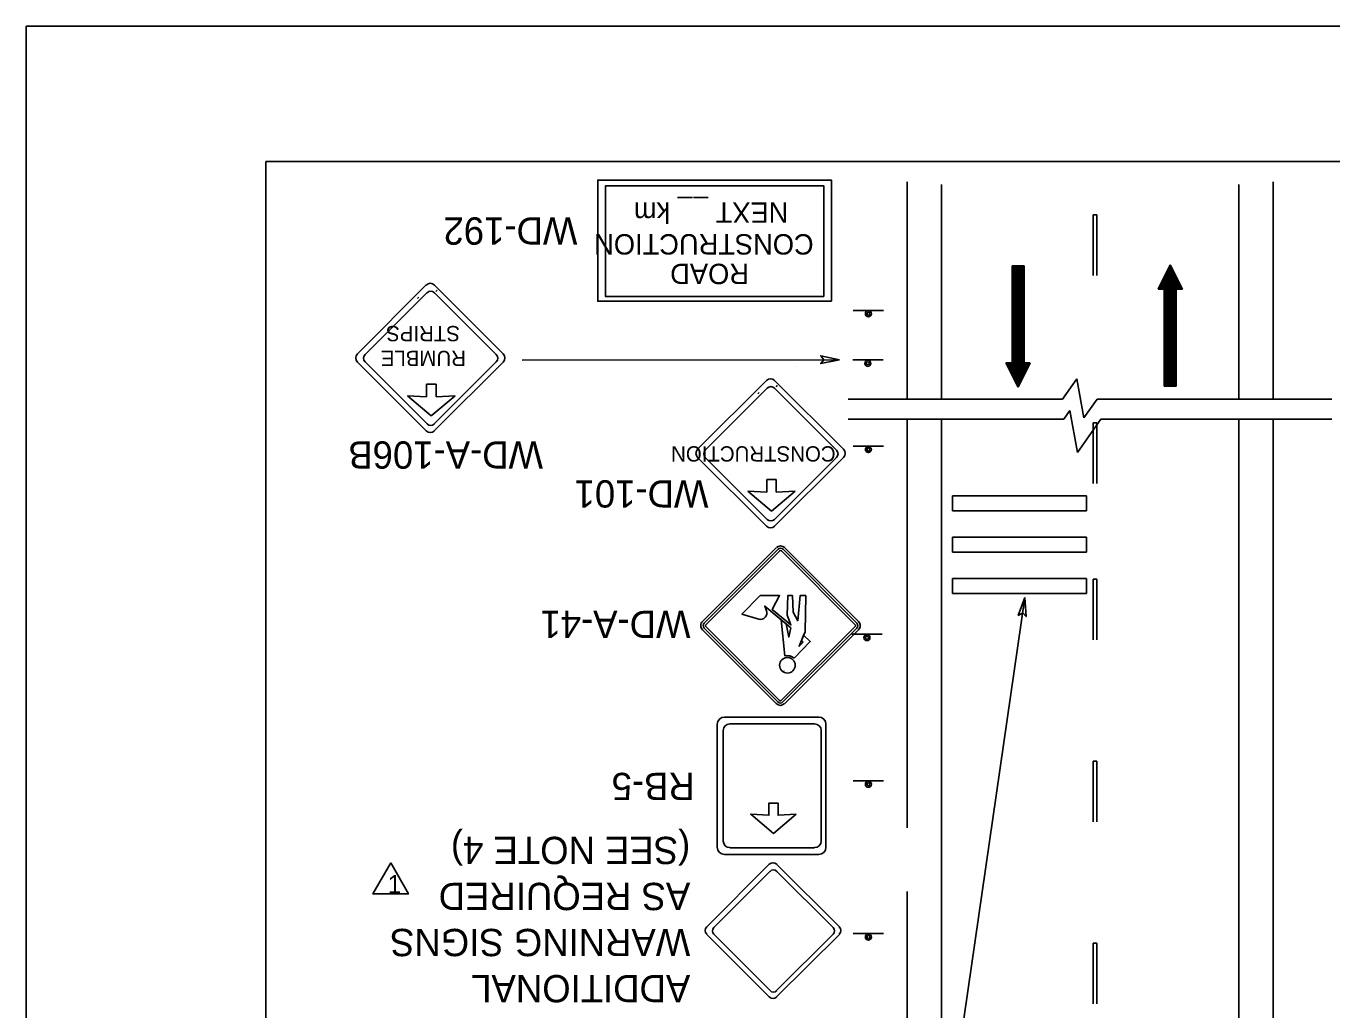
# Model space of a CAD drawing. Extents: x 1372 to 1588, y 125 to 404.
# Drawn here: x 1372.1 to 1476.2, y 325.5 to 404 of the extents above; entities that cross this region are included whole.
import ezdxf

# ---------------------------------------------------------------- set-up
doc = ezdxf.new("R2010")
doc.units = 0
for name, color, linetype in [('Level 1', 7, 'Continuous'), ('Level 10', 7, 'Continuous'), ('Level 2', 7, 'Continuous'), ('Level 44', 7, 'Continuous'), ('Level 5', 7, 'Continuous'), ('Level 60', 7, 'Continuous')]:
    doc.layers.add(name, color=color, linetype=linetype)

msp = doc.modelspace()

# ---------------------------------------------------------------- linework, layer by layer
at = {"layer": 'Level 1'}
for p, q in [((1431.88, 362.39), (1426, 356.51)), ((1438.43, 356.51), (1432.55, 362.39)), ((1432.02, 362.26), (1426.13, 356.38)), ((1432.15, 362.13), (1426.26, 356.25)), ((1438.17, 356.24), (1432.29, 362.13)), ((1438.3, 356.38), (1432.42, 362.26)), ((1426, 355.85), (1431.88, 349.96)), ((1426.13, 355.98), (1432.01, 350.09)), ((1426.26, 356.11), (1432.14, 350.22)), ((1432.28, 350.22), (1438.17, 356.1)), ((1432.41, 350.09), (1438.3, 355.97)), ((1432.55, 349.96), (1438.43, 355.84)), ((1432.49, 352.54), (1432.5, 352.54))]:
    msp.add_line(p, q, dxfattribs=at)
for points in [[(1430.49, 356.69), (1429.14, 357.1), (1430.6, 358.57), (1432.14, 358.57), (1431.56, 357.46), (1433.05, 356.24), (1432.76, 357.02), (1432.8, 358.57), (1433.16, 358.57), (1433.23, 357.25), (1433.59, 356.57), (1433.78, 358.57), (1434.23, 358.57), (1434.17, 355.69), (1433.7, 354.53), (1434.03, 354.87)], [(1430.49, 356.69), (1429.14, 357.1), (1430.6, 358.57), (1432.14, 358.57), (1431.56, 357.46), (1433.05, 356.24), (1432.76, 357.02), (1432.8, 358.57), (1433.16, 358.57), (1433.23, 357.25), (1433.59, 356.57), (1433.78, 358.57), (1434.23, 358.57), (1434.17, 355.69), (1433.7, 354.53), (1434.03, 354.87)], [(1430.49, 356.69), (1429.14, 357.1), (1430.6, 358.57), (1432.14, 358.57), (1431.56, 357.46), (1433.05, 356.24), (1432.76, 357.02), (1432.8, 358.57), (1433.16, 358.57), (1433.23, 357.25), (1433.59, 356.57)], [(1433.59, 356.57), (1433.78, 358.57), (1434.23, 358.57), (1434.17, 355.69), (1434.06, 355.41), (1434.59, 354.91), (1433.31, 353.58)], [(1432.57, 353.77), (1432.27, 356.64), (1432.66, 356.33), (1432.88, 355.26), (1433.05, 356), (1430.96, 357.73), (1431.1, 357.36)], [(1432.57, 353.77), (1432.27, 356.64), (1432.66, 356.33), (1432.88, 355.26), (1433.05, 356), (1430.96, 357.73), (1431.1, 357.36)], [(1432.57, 353.77), (1432.27, 356.64), (1430.96, 357.73), (1431.1, 357.36)], [(1434.03, 354.87), (1433.89, 354.99), (1434.06, 355.41), (1434.59, 354.91), (1433.31, 353.58)], [(1434.03, 354.87), (1433.89, 354.99), (1434.06, 355.41), (1434.59, 354.91), (1433.31, 353.58)]]:
    msp.add_lwpolyline(points, dxfattribs=at)
for points in [[(1432.66, 356.33), (1432.88, 355.26), (1433.05, 356)], [(1434.03, 354.87), (1433.89, 354.99), (1433.7, 354.53)], [(1401.13, 337.26), (1399.71, 334.79), (1402.55, 334.79)]]:
    msp.add_lwpolyline(points, close=True, dxfattribs=at)
msp.add_circle((1432.77, 353.02), 0.624, dxfattribs=at)
msp.add_circle((1432.77, 353.02), 0.624, dxfattribs=at)
msp.add_circle((1432.77, 353.02), 0.624, dxfattribs=at)
for centre, radius, start, end in [((1432.22, 362.06), 0.471, 45, 134.9652), ((1432.22, 362.06), 0.285, 45, 134.9652), ((1432.22, 362.06), 0.1, 45, 134.9652), ((1430.63, 357.18), 0.502, 253.381, 21.0999), ((1430.63, 357.18), 0.502, 253.381, 21.0999), ((1430.63, 357.18), 0.502, 253.381, 21.0999), ((1426.33, 356.18), 0.471, 134.9651, 225), ((1426.33, 356.18), 0.285, 134.9651, 225), ((1426.33, 356.18), 0.1, 134.9651, 225), ((1438.1, 356.17), 0.1, 314.965, 45), ((1438.1, 356.17), 0.285, 314.965, 45), ((1438.1, 356.17), 0.471, 314.965, 45), ((1432.77, 353.02), 0.775, 46.3135, 104.9576), ((1432.77, 353.02), 0.775, 46.3135, 104.9576), ((1432.77, 353.02), 0.775, 46.3135, 104.9576), ((1432.21, 350.29), 0.471, 225, 314.9651), ((1432.21, 350.29), 0.285, 225, 314.9651), ((1432.21, 350.29), 0.1, 225, 314.9651)]:
    msp.add_arc(centre, radius, start, end, dxfattribs=at)
at = {"layer": 'Level 10'}
for p, q in [((1442.33, 391.56), (1442.33, 374.24)), ((1471.51, 391.56), (1471.51, 374.24)), ((1445.05, 391.35), (1445.05, 374.24)), ((1468.76, 391.35), (1468.76, 374.24)), ((1450.68, 377.12), (1450.68, 384.86)), ((1451.65, 384.86), (1450.68, 384.86)), ((1450.68, 376.15), (1450.68, 384.86)), ((1450.8, 375.91), (1450.8, 384.86)), ((1450.92, 375.67), (1450.92, 384.86)), ((1451.04, 375.42), (1451.04, 384.86)), ((1451.16, 375.18), (1451.16, 384.86)), ((1451.28, 375.42), (1451.28, 384.86)), ((1451.4, 375.67), (1451.4, 384.86)), ((1451.52, 375.91), (1451.52, 384.86)), ((1451.65, 377.12), (1451.65, 384.86)), ((1451.65, 376.15), (1451.65, 384.86)), ((1463.3, 384.94), (1462.33, 383)), ((1463.06, 384.45), (1463.06, 375.26)), ((1463.18, 384.69), (1463.18, 375.26)), ((1463.3, 384.94), (1463.3, 375.26)), ((1463.3, 384.94), (1464.27, 383)), ((1463.42, 384.69), (1463.42, 375.26)), ((1463.54, 384.45), (1463.54, 375.26)), ((1462.45, 383.24), (1462.45, 383)), ((1462.57, 383.49), (1462.57, 383)), ((1462.69, 383.73), (1462.69, 383)), ((1462.82, 383.97), (1462.82, 375.26)), ((1462.94, 384.21), (1462.94, 375.26)), ((1463.66, 384.21), (1463.66, 375.26)), ((1463.78, 383.97), (1463.78, 375.26)), ((1463.9, 383.73), (1463.9, 383)), ((1464.03, 383.49), (1464.03, 383)), ((1464.15, 383.24), (1464.15, 383)), ((1462.33, 383), (1462.82, 383)), ((1462.82, 383), (1462.82, 375.26)), ((1463.78, 383), (1463.78, 375.26)), ((1463.78, 383), (1464.27, 383)), ((1451.16, 375.18), (1450.19, 377.12)), ((1450.68, 377.12), (1450.19, 377.12)), ((1450.32, 376.87), (1450.32, 377.12)), ((1450.44, 376.63), (1450.44, 377.12)), ((1450.56, 376.39), (1450.56, 377.12)), ((1451.16, 375.18), (1452.13, 377.12)), ((1452.13, 377.12), (1451.65, 377.12)), ((1451.77, 376.39), (1451.77, 377.12)), ((1451.89, 376.63), (1451.89, 377.12)), ((1452.01, 376.87), (1452.01, 377.12)), ((1462.82, 375.26), (1463.78, 375.26)), ((1442.33, 372.63), (1442.33, 340.05)), ((1445.05, 372.63), (1445.05, 157.87)), ((1468.76, 372.63), (1468.76, 157.87)), ((1471.51, 372.63), (1471.51, 202.79)), ((1456.61, 366.53), (1445.93, 366.53)), ((1445.93, 366.53), (1445.93, 365.33)), ((1456.61, 365.33), (1456.61, 366.53)), ((1445.93, 365.33), (1456.61, 365.33)), ((1445.93, 362.03), (1445.93, 363.23)), ((1445.93, 363.23), (1456.61, 363.23)), ((1456.61, 363.23), (1456.61, 362.03)), ((1456.61, 362.03), (1445.93, 362.03)), ((1456.61, 359.93), (1445.93, 359.93)), ((1445.93, 359.93), (1445.93, 358.73)), ((1456.61, 358.73), (1456.61, 359.93)), ((1445.93, 358.73), (1456.61, 358.73)), ((1442.33, 157.87), (1442.33, 334.98))]:
    msp.add_line(p, q, dxfattribs=at)
at = {"layer": 'Level 2'}
for p, q in [((1457.15, 388.93), (1457.15, 384.09)), ((1457.44, 388.93), (1457.15, 388.93)), ((1457.44, 384.09), (1457.44, 388.93)), ((1403.27, 382.26), (1403.37, 382.37)), ((1404.73, 382.83), (1404.83, 382.93)), ((1431.86, 375.22), (1431.96, 375.32)), ((1430.4, 374.65), (1430.51, 374.76)), ((1457.15, 372.34), (1457.15, 367.5)), ((1457.44, 372.34), (1457.15, 372.34)), ((1457.44, 367.5), (1457.44, 372.34)), ((1457.15, 359.87), (1457.15, 355.04)), ((1457.44, 359.87), (1457.15, 359.87)), ((1457.44, 355.04), (1457.44, 359.87)), ((1457.15, 345.36), (1457.15, 340.52)), ((1457.44, 345.36), (1457.15, 345.36)), ((1457.44, 340.52), (1457.44, 345.36)), ((1457.15, 330.85), (1457.15, 326.01)), ((1457.44, 330.85), (1457.15, 330.85)), ((1457.44, 326.01), (1457.44, 330.85))]:
    msp.add_line(p, q, dxfattribs=at)
for points in [[(1436.27, 382.04), (1417.64, 382.04), (1417.64, 391.7), (1436.27, 391.7)], [(1435.68, 382.42), (1418.26, 382.42), (1418.26, 391.23), (1435.68, 391.23)]]:
    msp.add_lwpolyline(points, close=True, dxfattribs=at)
at = {"layer": 'Level 44'}
for p, q in [((1403.96, 383.34), (1398.48, 377.85)), ((1410.1, 377.85), (1404.61, 383.34)), ((1399.09, 377.79), (1404.03, 382.73)), ((1404.61, 382.73), (1409.55, 377.79)), ((1440.44, 381.31), (1438.02, 381.31)), ((1398.48, 377.19), (1403.96, 371.71)), ((1404.03, 372.26), (1399.09, 377.2)), ((1409.55, 377.2), (1404.61, 372.26)), ((1404.61, 371.71), (1410.1, 377.19)), ((1410.1, 377.85), (1410.1, 377.85)), ((1440.4, 377.36), (1437.98, 377.36)), ((1433.44, 376.82), (1433.44, 376.82)), ((1404.75, 375.43), (1403.99, 375.43)), ((1403.99, 375.43), (1403.99, 374.42)), ((1404.75, 374.42), (1404.75, 375.43)), ((1431.09, 375.73), (1425.61, 370.24)), ((1426.22, 370.18), (1431.16, 375.12)), ((1437.24, 370.24), (1431.74, 375.73)), ((1431.74, 375.12), (1436.69, 370.18)), ((1454.71, 374.24), (1455.85, 375.86)), ((1455.85, 375.86), (1456.41, 372.74)), ((1403.99, 374.42), (1402.48, 374.5)), ((1402.48, 374.5), (1404.37, 372.91)), ((1404.37, 372.91), (1406.26, 374.5)), ((1406.26, 374.5), (1404.75, 374.42)), ((1437.62, 374.24), (1454.71, 374.24)), ((1456.41, 372.74), (1457.47, 374.24)), ((1457.47, 374.24), (1476.18, 374.24)), ((1454.8, 372.63), (1455.3, 373.32)), ((1455.3, 373.32), (1455.89, 369.97)), ((1437.62, 372.63), (1454.8, 372.63)), ((1455.89, 369.97), (1457.77, 372.63)), ((1457.77, 372.63), (1476.18, 372.63)), ((1437.23, 370.24), (1437.24, 370.24)), ((1440.44, 370.49), (1438.02, 370.49)), ((1425.61, 369.59), (1431.09, 364.1)), ((1431.16, 364.65), (1426.22, 369.59)), ((1431.74, 364.1), (1437.24, 369.59)), ((1436.69, 369.59), (1431.74, 364.65)), ((1431.12, 367.82), (1431.12, 366.81)), ((1431.88, 367.82), (1431.13, 367.82)), ((1431.88, 366.81), (1431.88, 367.82)), ((1431.12, 366.81), (1429.61, 366.89)), ((1429.61, 366.89), (1431.5, 365.3)), ((1431.5, 365.3), (1433.39, 366.89)), ((1433.39, 366.89), (1431.88, 366.81)), ((1440.32, 355.49), (1437.9, 355.49)), ((1438.02, 355.58), (1438.02, 355.58)), ((1427.75, 348.89), (1435.27, 348.89)), ((1427.17, 338.51), (1427.17, 348.31)), ((1427.65, 339), (1427.65, 347.81)), ((1428.17, 348.34), (1434.94, 348.34)), ((1435.46, 347.82), (1435.46, 347.81)), ((1435.46, 347.81), (1435.46, 339)), ((1435.84, 348.31), (1435.84, 338.51)), ((1435.84, 348.31), (1435.84, 348.31)), ((1440.44, 343.8), (1438.02, 343.8)), ((1434.94, 338.47), (1428.17, 338.47)), ((1435.27, 337.93), (1427.75, 337.93)), ((1431.32, 337.15), (1426.34, 332.16)), ((1426.89, 332.1), (1431.38, 336.59)), ((1436.91, 332.16), (1431.91, 337.15)), ((1431.91, 336.59), (1436.41, 332.1)), ((1426.34, 331.56), (1431.32, 326.58)), ((1431.38, 327.08), (1426.89, 331.57)), ((1436.41, 331.57), (1431.91, 327.08)), ((1431.91, 326.58), (1436.91, 331.56)), ((1436.9, 332.16), (1436.91, 332.16)), ((1437.21, 331.86), (1437.21, 331.86)), ((1440.44, 331.62), (1438.02, 331.62))]:
    msp.add_line(p, q, dxfattribs=at)
msp.add_lwpolyline([(1433.47, 341.14), (1431.66, 339.61), (1429.84, 341.14), (1431.29, 341.06), (1431.29, 342.03), (1432.02, 342.03), (1432.02, 341.06)], close=True, dxfattribs=at)
for centre, radius in [((1439.23, 381.04), 0.242), ((1439.23, 381.04), 0.121), ((1439.18, 377.09), 0.242), ((1439.18, 377.09), 0.121), ((1439.23, 370.22), 0.242), ((1439.23, 370.22), 0.121), ((1439.11, 355.22), 0.242), ((1439.11, 355.22), 0.121), ((1439.23, 343.53), 0.242), ((1439.23, 343.53), 0.121), ((1439.23, 331.35), 0.242), ((1439.23, 331.35), 0.121)]:
    msp.add_circle(centre, radius, dxfattribs=at)
for centre, radius, start, end in [((1404.29, 383.01), 0.459, 45, 135), ((1404.32, 382.43), 0.413, 45, 135), ((1398.8, 377.52), 0.459, 135, 225), ((1399.38, 377.49), 0.413, 135, 225), ((1409.26, 377.49), 0.413, 315, 45), ((1409.77, 377.52), 0.459, 315, 45), ((1431.42, 375.4), 0.459, 45, 135), ((1431.45, 374.82), 0.413, 45, 135), ((1404.32, 372.55), 0.413, 225, 315), ((1404.29, 372.03), 0.459, 225, 315), ((1425.93, 369.91), 0.459, 135, 225), ((1426.51, 369.88), 0.413, 135, 225), ((1436.39, 369.88), 0.413, 315, 45), ((1436.91, 369.91), 0.459, 315, 45), ((1431.45, 364.94), 0.413, 225, 315), ((1431.42, 364.42), 0.459, 225, 315), ((1427.75, 348.31), 0.58, 90, 180), ((1435.26, 348.31), 0.58, 360, 90), ((1428.17, 347.82), 0.522, 90, 180), ((1434.94, 347.82), 0.522, 360, 90), ((1427.75, 338.51), 0.58, 180, 270), ((1428.17, 339), 0.522, 180, 270), ((1434.94, 339), 0.522, 270, 360), ((1435.26, 338.51), 0.58, 270, 360), ((1431.62, 336.85), 0.418, 45, 135), ((1431.65, 336.32), 0.376, 45, 135), ((1426.63, 331.86), 0.418, 135, 225), ((1427.16, 331.83), 0.376, 135, 225), ((1436.14, 331.83), 0.376, 315, 45), ((1436.61, 331.86), 0.418, 315, 45), ((1431.65, 327.34), 0.376, 225, 315), ((1431.62, 326.87), 0.418, 225, 315)]:
    msp.add_arc(centre, radius, start, end, dxfattribs=at)
at = {"layer": 'Level 5'}
for p, q in [((1436.93, 377.36), (1411.62, 377.34)), ((1451.71, 358.43), (1440.67, 282.3))]:
    msp.add_line(p, q, dxfattribs=at)
for points in [[(1436.93, 377.36), (1435.42, 377.07), (1435.67, 377.38), (1435.43, 377.69)], [(1451.71, 358.43), (1451.8, 356.9), (1451.53, 357.19), (1451.18, 356.99)]]:
    msp.add_lwpolyline(points, close=True, dxfattribs=at)
at = {"layer": 'Level 60'}
msp.add_line((1372.06, 403.98), (1372.06, 403.98), dxfattribs=at)
for points in [[(1372.06, 403.98), (1588.06, 403.98), (1588.06, 124.98), (1372.06, 124.98)], [(1391.18, 393.17), (1578.06, 393.17), (1578.06, 135.79), (1391.18, 135.79)]]:
    msp.add_lwpolyline(points, close=True, dxfattribs=at)

# ---------------------------------------------------------------- texts
at = {"layer": 'Level 1'}
msp.add_text('1', height=1.45, rotation=360, dxfattribs=at).set_placement((1400.9, 334.84))
at = {"layer": 'Level 10'}
for s, p in [('WD-192', (1416.02, 388.73)), ('WD-A-106B', (1413.28, 370.87)), ('WD-101', (1426.47, 367.77)), ('WD-A-41', (1425.04, 357.36)), ('RB-5', (1425.38, 344.44)), ('(SEE NOTE 4)', (1425.02, 339.34)), ('AS REQUIRED', (1425.02, 335.67)), ('WARNING SIGNS', (1425.02, 332)), ('ADDITIONAL', (1425.02, 328.32))]:
    msp.add_text(s, height=2.177, rotation=180, dxfattribs=at).set_placement(p)
at = {"layer": 'Level 44'}
for s, height, p in [('NEXT __ km', 1.625, (1432.84, 389.92)), ('CONSTRUCTION', 1.625, (1434.86, 387.39)), ('ROAD', 1.625, (1429.7, 385.03)), ('STRIPS', 1.218, (1406.65, 380.07)), ('RUMBLE', 1.218, (1407.13, 378.09)), ('CONSTRUCTION', 1.2178, (1436.61, 370.48))]:
    msp.add_text(s, height=height, rotation=180, dxfattribs=at).set_placement(p)

doc.saveas('drawing.dxf')
